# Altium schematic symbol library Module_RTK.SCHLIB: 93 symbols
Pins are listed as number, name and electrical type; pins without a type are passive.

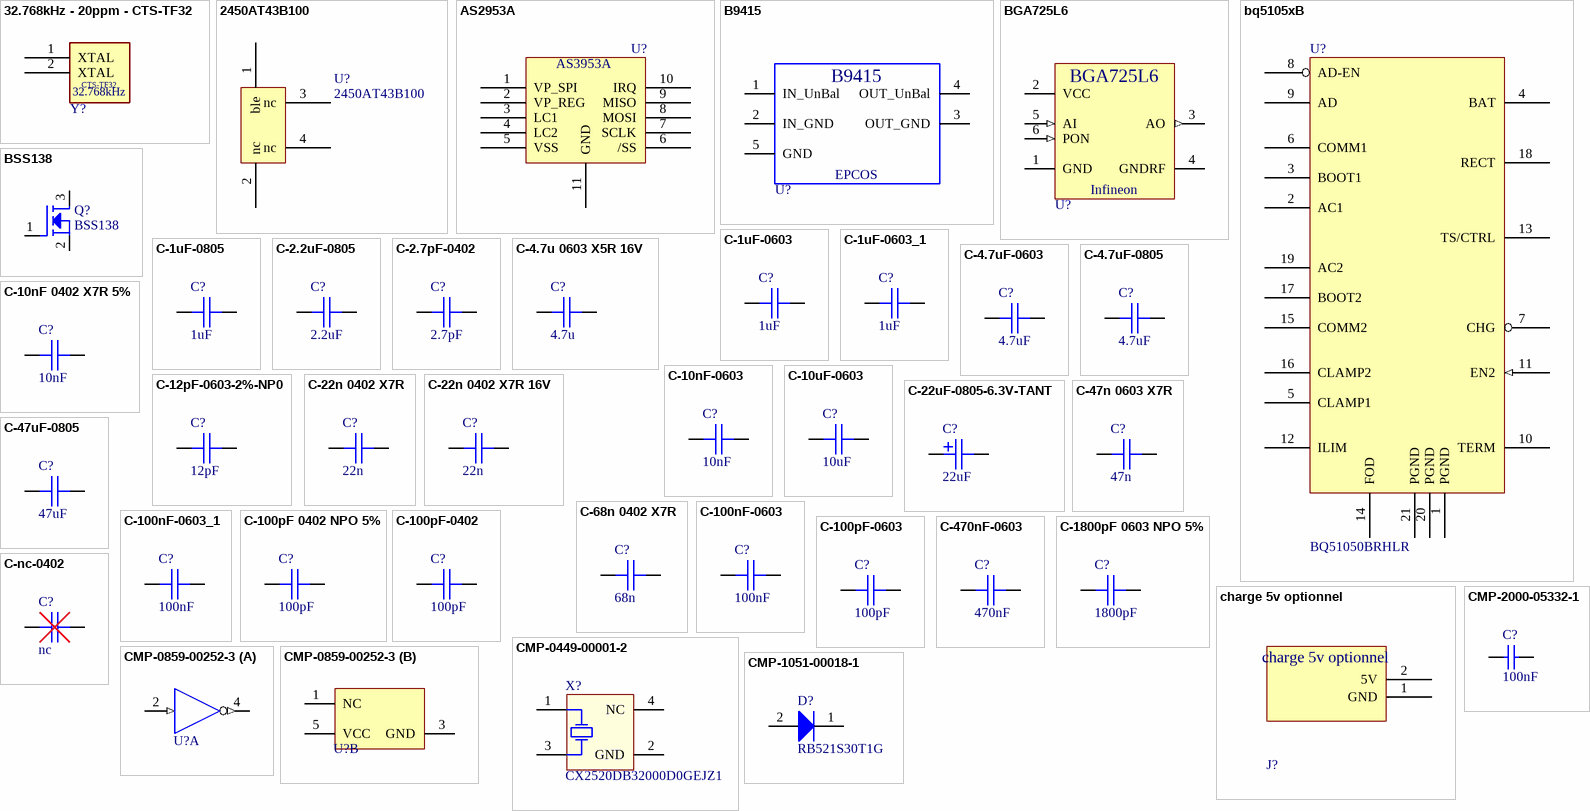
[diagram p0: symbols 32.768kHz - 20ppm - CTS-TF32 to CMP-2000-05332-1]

## 32.768kHz - 20ppm - CTS-TF32
designator Y?  (value not drawn)
footprint CTS-TF32 (3.2mm x 1.5mm)
pins: 1 XTAL, 2 XTAL

## 2450AT43B100
designator U?
ble ant 2.4 GHz
footprint 2450AT43B100 (ble ant 2.4 GHz)
pins: 1 ble, 2 nc, 3 nc, 4 nc

## AS2953A
designator U?, comment AS3953A  (value not drawn)
footprint MLPD_3x3mm_10_pin_AS3953A (PSON, 10-Leads, Body 3,00x3,00mm, Pitch 0,50mm, Thermal Pad 2,36x1,63mm, IPC Medium Density)
pins: 1 VP_SPI, 2 VP_REG, 3 LC1, 4 LC2, 5 VSS, 6 /SS, 7 SCLK, 8 MOSI, 9 MISO, 10 IRQ, 11 GND

## B9415
designator U?  (value not drawn)
SAW filter; PartNumber: BGA725L6; Manufacturer: Infineon; Gain (typ): 20 dB; F (typ): 0.65 dB; I (typ): 3.6 mA; Frequency (f): 1550 - 1615 MHz; Green: yes; P-1dB (in): -16
footprint B9415
pins: 1 IN_UnBal (power) "General ground", 2 IN_GND (power) "DC supply", 3 OUT_GND (power) "DC supply", 4 OUT_UnBal (power) "LNA RF ground", 5 GND (power) "DC supply"

## BGA725L6
designator U?  (value not drawn)
Silicon Germanium Low Noise Amplifier for Global Navigation Satellite Systems (GNSS), 1550 - 1615 MHz, 20 dB Gain, TSLP-6-2, Green; Manufacturer: Infineon; Gain (typ): 20 dB; F (typ): 0.65 dB; I (typ): 3.6 mA; Green: yes; P-1dB (in): -16
footprint INF-TSLP-6-2_V (TSLP, 6-Leads, Body 0.7x1.1 mm)
pins: 1 GND (power) "General ground", 2 VCC (power) "DC supply", 3 AO (out) "LNA output", 4 GNDRF (power) "LNA RF ground", 5 AI (in) "LNA input", 6 PON (in) "Power on control"

## bq5105xB
designator U?, comment BQ51050BRHLR
footprint RHL20-3050X2050TP (QFN, 20-Leads, Body 4.5x3.5mm, Pitch 0.5mm, Thermal Pad 3.05x2.05mm, TI Recommended)
pins: 1 PGND (power), 2 AC1, 3 BOOT1, 4 BAT, 5 CLAMP1, 6 COMM1, 7 CHG (oc), 8 AD-EN, 9 AD, 10 TERM, 11 EN2 (in), 12 ILIM, 13 TS/CTRL, 14 FOD, 15 COMM2, 16 CLAMP2, 17 BOOT2, 18 RECT, 19 AC2, 20 PGND (power), 21 PGND (power)

## BSS138
designator Q?
MOSFET N-CH 50V 200MA SOT23-3; Manufacturer: Diodes Inc; RefMfg: BSS138-7-F
footprint SOT23_0.915
pins: 1 G, 2 S, 3 D

## C-1uF-0603
designator C?  value 1uF  (hidden comment: C-1uF-0603)
Voltage: 25V; Fabricant_Ref: GRM188R71E104JA01D; Fabricant: Murata; Technologie: 5%
simulation model CAP
footprint SM/C_0603
pins: 1, 2
1 alternate drawing of the same symbol

## C-1uF-0603_1
designator C?, comment value 1uF  (hidden comment: C-1uF-0603)
Voltage: 16V; Fabricant_Ref: C1608X7R1C105K080AC; Fabricant: Murata; Tolerance: 10%; Technologie: X7R
simulation model CAP
footprint SM/C_0603
pins: 1, 2
1 alternate drawing of the same symbol

## C-1uF-0805
designator C?  value 1uF  (hidden comment: C-1uF-0805)
Voltage: 16V; Fabricant_Ref: GRM188R71E104JA01D; Fabricant: Murata; Tolerance: 10%; Technologie: X7R
simulation model CAP
footprint SM/C_0805
pins: 1, 2
1 alternate drawing of the same symbol

## C-2.2uF-0805
designator C?  value 2.2uF  (hidden comment: C-2.2uF-0805)
Voltage: 16V; Fabricant_Ref: C2012X7R1C225K125AB; Fabricant: Murata; Tolerance: 10%; Technologie: X7R
simulation model CAP
footprint SM/C_0805
pins: 1, 2
1 alternate drawing of the same symbol

## C-2.7pF-0402
designator C?  value 2.7pF  (hidden comment: C-2.7pF-0402)
Voltage: 50V; Fabricant_Ref: GRM1555C1H2R7BA01D; Fabricant: Murata; Tolerance: 0.1pF; Technologie: NPO
simulation model CAP
footprint SM/C_0402
pins: 1, 2
1 alternate drawing of the same symbol

## C-4.7u 0603 X5R 16V
designator C?  value 4.7u  (hidden comment: C-4.7u 0603 X5R 16V)
Fabricant_Ref: GRM188R61C475KAAJD; Fabricant: Murata; Tolerance: 10%
simulation model CAP
footprint SM/C_0603
pins: 1, 2
1 alternate drawing of the same symbol

## C-4.7uF-0603
designator C?  value 4.7uF  (hidden comment: C-4.7uF-0603)
Voltage: 6.3V; Fabricant_Ref: GRM188R60J475KE19D; Fabricant: Murata; Tolerance: 10%; Technologie: X5R
simulation model CAP
footprint SM/C_0603
pins: 1, 2
1 alternate drawing of the same symbol

## C-4.7uF-0805
designator C?  value 4.7uF  (hidden comment: C-4.7uF-0805)
Voltage: 10V; Fabricant_Ref: C2012X7R1A475K085AC; Fabricant: Murata; Tolerance: 10%; Technologie: X7R
simulation model CAP
footprint SM/C_0805
pins: 1, 2
1 alternate drawing of the same symbol

## C-10nF 0402 X7R 5%
designator C?  value 10nF  (hidden comment: C-10nF 0402 X7R 5%)
Voltage: 50V; Fabricant_Ref: C0402C103J5RACTU; Fabricant: KEMET
simulation model CAP
footprint SM/C_0402
pins: 1, 2
1 alternate drawing of the same symbol

## C-10nF-0603
designator C?  value 10nF  (hidden comment: C-10nF-0603)
Voltage: 50V; Fabricant_Ref: GRM188R71H103KA01D; Fabricant: Murata; Tolerance: 10%; Technologie: X7R
simulation model CAP
footprint SM/C_0603
pins: 1, 2
1 alternate drawing of the same symbol

## C-10uF-0603
designator C?  value 10uF  (hidden comment: C-10uF-0603)
Voltage: 6.3V; Fabricant_Ref: C1608X5R0J106M080AB; Fabricant: TDK; Tolerance: 20%; Technologie: X5R
simulation model CAP
footprint SM/C_0603
pins: 1, 2
1 alternate drawing of the same symbol

## C-12pF-0603-2%-NP0
designator C?  value 12pF  (hidden comment: C-12pF-0603-2%-NP0)
Fabricant: Murata; Fabricant_Ref: GRM1885C1H220JA01D; Technologie: NPO; Tolerance: 5%; Voltage: 50V
footprint SM/C_0603 (Footprint not found)
pins: 1, 2

## C-22n 0402 X7R
designator C?  value 22n  (hidden comment: C-22n 0402 X7R)
Voltage: 50V; Fabricant_Ref: GRM155R71H223KA12D; Fabricant: Murata; Tolerance: 10%
simulation model CAP
footprint SM/C_0402
pins: 1, 2
1 alternate drawing of the same symbol

## C-22n 0402 X7R 16V
designator C?  value 22n  (hidden comment: C-22n 0402 X7R 16V)
Fabricant_Ref: 0402YC223KAT2A; Fabricant: AVX; Tolerance: 10%
simulation model CAP
footprint SM/C_0402
pins: 1, 2
1 alternate drawing of the same symbol

## C-22uF-0805-6.3V-TANT
designator C?  value 22uF  (hidden comment: C-22uF-0805-6.3V-TANT)
Voltage: 6.3V; Fabricant_Ref: TLJP107M006R5400; Fabricant: AVX; Tolerance: 20%; Technologie: Tantale
simulation model CAP
footprint SM/C_0805_POL
pins: 1, 2
1 alternate drawing of the same symbol

## C-47n 0603 X7R
designator C?  value 47n  (hidden comment: C-47n 0603 X7R)
Voltage: 50V; Fabricant_Ref: GRM188R71H473KA61D; Fabricant: Murata; Tolerance: 10%
simulation model CAP
footprint SM/C_0603
pins: 1, 2
1 alternate drawing of the same symbol

## C-47uF-0805
designator C?  value 47uF  (hidden comment: C-47uF-0805)
Voltage: 6.3V; Fabricant_Ref: C2012X5R0J476M125AC; Fabricant: TDK; Tolerance: 20%; Technologie: X5R
simulation model CAP
footprint SM/C_0805
pins: 1, 2
1 alternate drawing of the same symbol

## C-68n 0402 X7R
designator C?  value 68n  (hidden comment: C-68n 0402 X7R)
Voltage: 50V; Fabricant_Ref: C1005X7R1H683K050BB; Fabricant: TDK; Tolerance: 10%
simulation model CAP
footprint SM/C_0402
pins: 1, 2
1 alternate drawing of the same symbol

## C-100nF-0603
designator C?  value 100nF  (hidden comment: C-100nF-0603)
Voltage: 25V; Fabricant_Ref: GRM188R71E104JA01D; Fabricant: Murata; Technologie: 5%
simulation model CAP
footprint SM/C_0603
pins: 1, 2
1 alternate drawing of the same symbol

## C-100nF-0603_1
designator C?, comment value 100nF  (hidden comment: C-100nF-0603)
Voltage: 25V; Fabricant_Ref: C1608X7R1E104K080AA; Fabricant: TDK; Tolerance: 10%; Technologie: X7R
simulation model CAP
footprint SM/C_0603
pins: 1, 2
1 alternate drawing of the same symbol

## C-100pF 0402 NPO 5%
designator C?  value 100pF  (hidden comment: C-100pF 0402 NPO 5%)
Voltage: 50V; Fabricant_Ref: 500R07N101JV4T; Fabricant: Johanson Dielectrics
simulation model CAP
footprint SM/C_0402
pins: 1, 2
1 alternate drawing of the same symbol

## C-100pF-0402
designator C?  value 100pF  (hidden comment: C-100pF-0402)
Voltage: 50V; Fabricant_Ref: GRM1555C1H101FA01J; Fabricant: Murata; Tolerance: 1%; Technologie: NPO
simulation model CAP
footprint SM/C_0402
pins: 1, 2
1 alternate drawing of the same symbol

## C-100pF-0603
designator C?  value 100pF  (hidden comment: C-100pF-0603)
Voltage: 100V; Fabricant_Ref: GRM1885C2A101JA01D; Fabricant: Murata; Tolerance: 5%; Technologie: NPO
simulation model CAP
footprint SM/C_0603
pins: 1, 2
1 alternate drawing of the same symbol

## C-470nF-0603
designator C?  value 470nF  (hidden comment: C-470nF-0603)
Fabricant: Samsung; Fabricant_Ref: CL10B104JA8NNNC; Technologie: X7R; Tolerance: 5%; Voltage: 25V
footprint SM/C_0603 (Footprint not found)
pins: 1, 2

## C-1800pF 0603 NPO 5%
designator C?  value 1800pF  (hidden comment: C-1800pF 0603 NPO 5%)
Voltage: 50V; Fabricant_Ref: GRM1885C1H182JA01D; Fabricant: Murata
simulation model CAP
footprint SM/C_0603
pins: 1, 2
1 alternate drawing of the same symbol

## C-nc-0402
designator C?  value nc  (hidden comment: C-nc-0402)
Technologie: NPO
simulation model CAP
footprint SM/C_0402 (Footprint not found)
pins: 1, 2
1 alternate drawing of the same symbol

## charge 5v optionnel
designator J?  (value not drawn)
connecteur de charge 5v si jamais il y avais des problemes avec la charge par induction. (fils a souder directement sur le pcb, pas de connecteur externe)
pins: 1 GND, 2 5V

## CMP-0449-00001-2
designator X?, comment CX2520DB32000D0GEJZ1
Crystal, 32 MHz, 8 pF, -10 to 70 degC, Surface Mount 2.5 x 2.0 mm; Manufacturer: Kyocera; Manufacturer 1: Kyocera AVX; Load Capacitance: 8 pF; Frequency Range: 32000 kHz; Packing: Tape and Reel; Motional Series Resistance: 50 ohm (max); Drive Level: 10uW (100uW max.)
footprint AVX-CX2520DB32000D0GEJZ1-4_V (Hand Drawn, 4-Leads,Body 2.5x2mm)
pins: 1 HOT, 2 GND (power), 3 HOT, 4 NC

## CMP-0859-00252-3
designator U?, comment SN74LVC1G04DCKR  (value not drawn)
Single Inverter, DCK0005A, LARGE T&R; Manufacturer: Texas Instruments; Input Type: CMOS/TTL; Output Drive (IOL/IOH)(Max)(mA): 32/-32; Sub-Family: Inverting Buffer/Driver; VCC(Min)(V): 1.65; Bits(#): 1; Schmitt Trigger: No; Technology Family: LVC; Rating: Catalog; ICC @ Nom Voltage(Max)(mA): 0.01; tpd @ Nom Voltage(Max)(ns): 7.5,5.2,4.2,3.7; Voltage(Nom)(V): 1.8,2.5,3.3,5; F @ Nom Voltage(Max)(Mhz): 150; Output Type: CMOS; VCC(Max)(V): 5.5; Logic: Inverting
footprint DCK0005A_N (SOT23, 5-Leads, Body 2.15x1.4mm, Pitch 0.65mm, IPC Medium Density)
footprint DCK0005A_L (SOT23, 5-Leads, Body 2.15x1.4mm, Pitch 0.65mm, IPC High Density)
footprint DCK0005A_M (SOT23, 5-Leads, Body 2.15x1.4mm, Pitch 0.65mm, IPC Low Density)
part A pins: 2 A (in) "Input A", 4 Y (out) "Output Y"
part B pins: 1 NC "Ground", 3 GND (power) "Ground Pin", 5 VCC (power) "Power Pin"

## CMP-1051-00018-1
designator D?, comment RB521S30T1G
Schottky Barrier Diode, 2-Pin SOD-523, Pb-Free, Tape and Reel; Manufacturer: On Semiconductor; Configuration: Single; IFSM Max (A): 1
footprint ONSC-SOD-523-2-502-01_V (SOD, 2-Leads, Body 1.2x0.8mm)
pins: 1 K, 2 A

## CMP-2000-05332-1
designator C?, comment 100nF
Multi-layer Ceramic Capacitor, -55 to 125 degC, 2-Pin SMD (0603), RoHS, Tape and Reel; Manufacturer: Samsung Electro-Mechanics; Manufacturer 1: Samsung; Manufacturer Part Number 1: CL10B104KB8NNNC; Capacitance: 0.1µF; Rated Voltage: 50V; Dielectric: X7R; Tolerance (%): ±10%
footprint SAMS-C0603-2_M (Chip Capacitor, 2-Leads, Body 1.70x0.90mm, IPC Low Density)
footprint SAMS-C0603-2_N (Footprint not found)
footprint SAMS-C0603-2_L (Chip Capacitor, 2-Leads, Body 1.70x0.90mm, IPC High Density)
pins: 1, 2

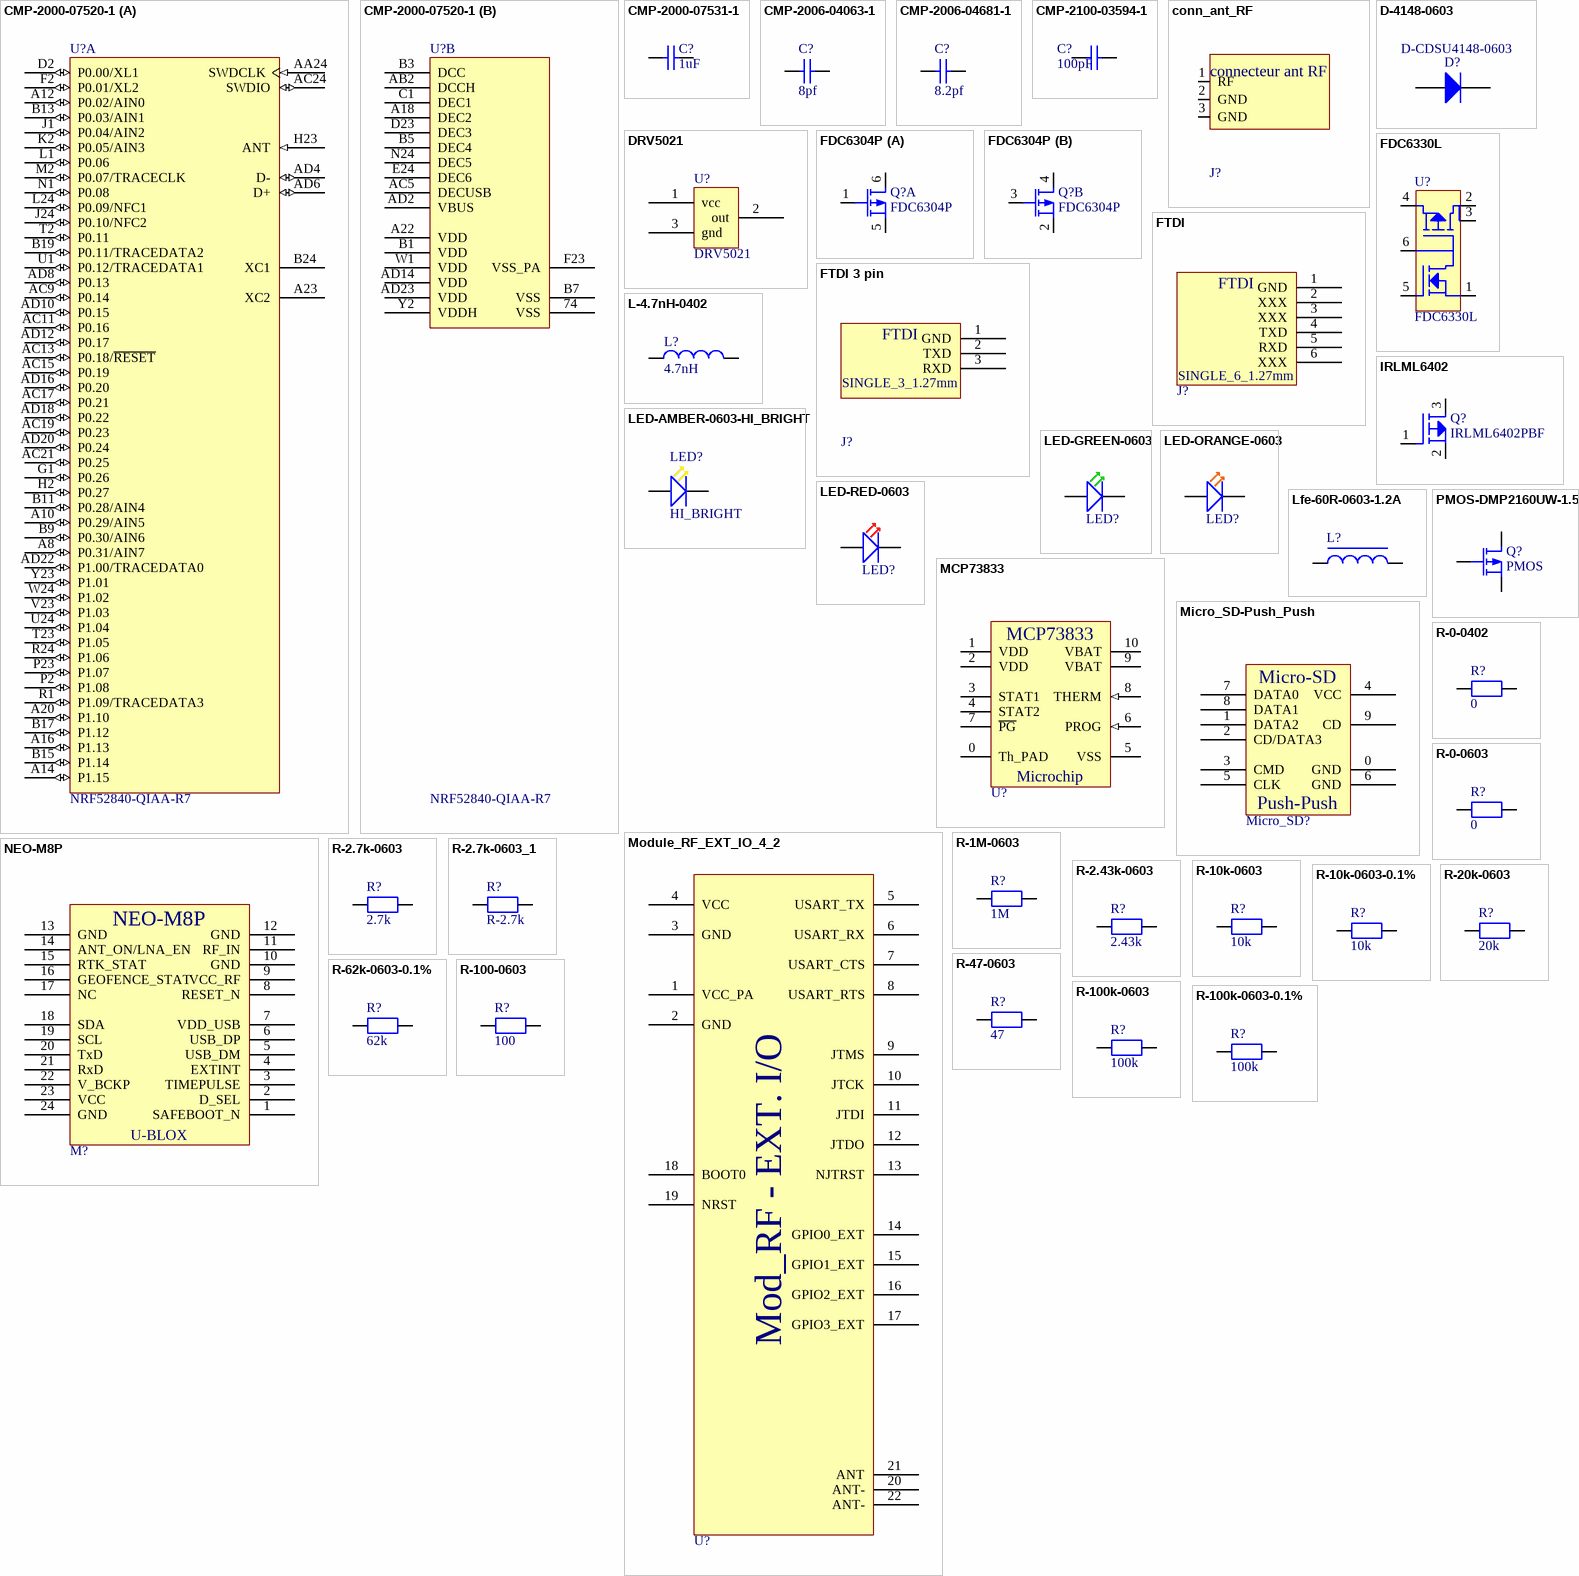
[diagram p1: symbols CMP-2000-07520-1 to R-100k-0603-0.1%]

## CMP-2000-07520-1
designator U?, comment NRF52840-QIAA-R7
RF System on a Chip, 1.7 to 3.6 V, -40 to 85 degC, 73-Pin AQFN, RoHS, Tape and Reel; Manufacturer: Nordic Semiconductor
footprint NRSC-AQFN-73 (AQFN, 73-Leads, Body 7x7mm, Pitch 0.5mm)
part A pins: A8 P0.31/AIN7 (io), A10 P0.29/AIN5 (io), A12 P0.02/AIN0 (io), A14 P1.15 (io) "General purpose I/O", A16 P1.13 (io) "General purpose I/O", A20 P1.10 (io) "General purpose I/O", A23 XC2 "Connection for 32 MHz crystal.", AA24 SWDCLK (in) "Serial wire debug clock input for debug and programming", AC9 P0.14 (io) "General purpose I/O", AC11 P0.16 (io) "General purpose I/O", AC13 P0.18/~{RESET} (io), AC15 P0.19 (io) "General purpose I/O", AC17 P0.21 (io) "General purpose I/O", AC19 P0.23 (io) "General purpose I/O", AC21 P0.25 (io) "General purpose I/O", AC24 SWDIO (io) "Debug serial data", AD4 D- (io) "USB D-", AD6 D+ (io) "USB D+", AD8 P0.13 (io) "General purpose I/O", AD10 P0.15 (io) "General purpose I/O", AD12 P0.17 (io) "General purpose I/O", AD16 P0.20 (io) "General purpose I/O", AD18 P0.22 (io) "General purpose I/O", AD20 P0.24 (io) "General purpose I/O", AD22 P1.00/TRACEDATA0 (io), B9 P0.30/AIN6 (io), B11 P0.28/AIN4 (io), B13 P0.03/AIN1 (io), B15 P1.14 (io) "General purpose I/O", B17 P1.12 (io) "General purpose I/O", B19 P0.11/TRACEDATA2 (io), B24 XC1 "Connection for 32 MHz crystal", D2 P0.00/XL1 (io), F2 P0.01/XL2 (io), G1 P0.26 (io) "General purpose I/O", H2 P0.27 (io) "General purpose I/O", H23 ANT (in) "Single-ended radio antenna connection", J1 P0.04/AIN2 (io), J24 P0.10/NFC2 (io), K2 P0.05/AIN3 (io), L1 P0.06 (io) "General purpose I/O", L24 P0.09/NFC1 (io), M2 P0.07/TRACECLK (io), N1 P0.08 (io) "General purpose I/O", P2 P1.08 (io) "General purpose I/O", P23 P1.07 (io) "General purpose I/O", R1 P1.09/TRACEDATA3 (io), R24 P1.06 (io) "General purpose I/O", T2 P0.11 (io) "General purpose I/O", T23 P1.05 (io) "General purpose I/O", U1 P0.12/TRACEDATA1 (io), U24 P1.04 (io) "General purpose I/O", V23 P1.03 (io) "General purpose I/O", W24 P1.02 (io) "General purpose I/O", Y23 P1.01 (io) "General purpose I/O"
part B pins: 74 VSS (power) "Ground pad. Exposed die pad must be connected to ground (VSS) for proper device operation.", A18 DEC2 (power) "1.3 V regulator supply decoupling (Radio supply)", A22 VDD (power) "Power supply", AB2 DCCH (power) "DC/DC converter output", AC5 DECUSB (power) "Decoupling for USB 3.3 V", AD2 VBUS (power) "5 V input for USB 3.3 V regulator", AD14 VDD (power) "Power supply", AD23 VDD (power) "Flash supply pad", B1 VDD (power) "Power supply", B3 DCC (power) "DC/DC converter output", B5 DEC4 (power) "1.3 V regulator supply decoupling", B7 VSS (power) "Ground", C1 DEC1 (power) "1.1 V regulator supply decoupling", D23 DEC3 (power) "Power supply, decoupling", E24 DEC6 (power) "1.3 V regulator supply decoupling (Radio supply)", F23 VSS_PA (power) "Ground (Radio supply)", N24 DEC5 (power) "1.3 V regulator supply decoupling (flash supply)", W1 VDD (power) "Power supply", Y2 VDDH (power) "High voltage power supply"

## CMP-2000-07531-1
designator C?, comment 1uF
Chip Capacitor, 1 uF, +/- 10%, 50 V, -55 to 125 degC, 0603 (1608 Metric), RoHS, Tape and Reel; Manufacturer: Taiyo Yuden; Manufacturer Part Number 1: UMK107AB7105KA-T; Voltage Rating: 50V; Dielectric: X7R
footprint CAPC1709X95X35LL10T25 (Chip Capacitor, 2-Leads, Body 1.75x0.95mm, IPC High Density)
footprint CAPC1709X95X35ML10T25 (Chip Capacitor, 2-Leads, Body 1.75x0.95mm, IPC Low Density)
footprint CAPC1709X95X35NL10T25 (Chip Capacitor, 2-Leads, Body 1.75x0.95mm, IPC Medium Density)
pins: 1, 2

## CMP-2006-04063-1
designator C?, comment 8pf
Manufacturer: AVX Interconnect / Elco; Part Number: 06031A8R0CAT2A; Manufacturer 1: Kyocera AVX
footprint CAPC1608X90X35LL15T15 (Chip Capacitor, 2-Leads, Body 1.60x0.81mm, IPC High Density)
footprint CAPC1608X90X35NL15T15 (Chip Capacitor, 2-Leads, Body 1.60x0.81mm, IPC Medium Density)
footprint CAPC1608X90X35ML15T15 (Chip Capacitor, 2-Leads, Body 1.60x0.81mm, IPC Low Density)
pins: 1, 2
1 alternate drawing of the same symbol

## CMP-2006-04681-1
designator C?, comment value 8.2pf  (hidden comment: 06032U8R2CAT2A)
Manufacturer: AVX Interconnect / Elco; Manufacturer 1: Kyocera AVX
footprint CAPC1508X91X25LL25T13 (Chip Capacitor, 2-Leads, Body 1.52x0.76mm, IPC High Density)
footprint CAPC1508X91X25ML25T13 (Chip Capacitor, 2-Leads, Body 1.52x0.76mm, IPC Low Density)
footprint CAPC1508X91X25NL25T13 (Chip Capacitor, 2-Leads, Body 1.52x0.76mm, IPC Medium Density)
pins: 1, 2
1 alternate drawing of the same symbol

## CMP-2100-03594-1
designator C?, comment Capacitance: 100pF  (hidden comment: CC0603JRNPO9BN101)
Chip Capacitor, 100 pF, +/- 5%, 50 V, -55 to 125 degC, 0603 (1608 Metric), RoHS, Tape and Reel; Manufacturer: Yageo; Voltage Rating (DC): 50V; Dielectric: C0G; Temperature Coefficient: 30ppm/degC; Insulation Resistance: 100GR
footprint CAPC1608X90X40ML10T20 (Chip Capacitor, 2-Leads, Body 1.7x0.9mm, IPC Low Density)
footprint CAPC1608X90X40NL10T20 (Chip Capacitor, 2-Leads, Body 1.60x0.80mm, IPC Medium Density)
footprint SM/C_0603
pins: 1, 2

## conn_ant_RF
designator J?, comment FTDI  (value not drawn)
pins: 1 RF, 2 GND, 3 GND

## D-4148-0603
designator D?, comment D-CDSU4148-0603
Fabricant: Comchip Technology; Fabricant_Ref: CSDU4148
footprint 0603/SOD-523F_Diode (SODFL, 2-Leads, Body 0,90x1,70mm, IPC Medium Density)
pins: 1 A, 2 K

## DRV5021
designator U?
Hall Effect Sensor
footprint SOT23 (SOT23, 3-Leads, Body 2,90x2,45mm, Pitch 0,95mm, IPC Medium Density)
pins: 1 vcc, 2 out, 3 gnd

## FDC6304P
designator Q?
Fabricant: Fairschild
footprint supersot_6
part A pins: 1 G1, 5 S1, 6 D1
part B pins: 2 S2, 3 G2, 4 D2

## FDC6330L
designator U?
IC LOAD SWITCH INT 20VIN SSOT-6; Manufacturer: Fairchild Semiconductor
footprint SOT-363_0.95 (TSOT-23, 6-Leads, Body 2.90x1.63mm, Pitch 0.95mm, IPC Medium Density)
pins: 1 R2, 2 D1Vout, 3 Vout, 4 Vin, 5 ON/OFF, 6 R1C1

## FTDI
designator J?  (value not drawn)
footprint SINGLE_6_1.27mm (Connector; Header; 6 Position)
pins: 1 GND, 2 XXX, 3 XXX, 4 TXD, 5 RXD, 6 XXX

## FTDI 3 pin
designator J?, comment FTDI  (value not drawn)
pins: 1 GND, 2 TXD, 3 RXD

## IRLML6402
designator Q?, comment IRLML6402PBF
MOSFET P-CH 20V 3.7A SOT-23; Manufacturer: International Rectifier; RefMfg: IRLML6402TRPBF
footprint SOT23_0.915
pins: 1 G, 2 S, 3 D

## L-4.7nH-0402
designator L?  value 4.7nH  (hidden comment: L-4.7nH-0402)
I_DC: 300mA; Tolerance: 0.3nH; Fabricant: Murata; Fabricant_Ref: LQG15HN3N3S02D
simulation model Model Name (Model Description)
footprint SM/L_0402
pins: 1, 2

## LED-AMBER-0603-HI_BRIGHT
designator LED?  (value not drawn)
footprint SM/D_0603 (Diode Package 0603)
pins: 1 A, 2 K

## LED-GREEN-0603
designator LED?  (value not drawn)
footprint SM/D_0603 (Diode Package 0603)
pins: 1 A, 2 K

## LED-ORANGE-0603
designator LED?  (value not drawn)
footprint SM/D_0603 (Diode Package 0603)
pins: 1 A, 2 K

## LED-RED-0603
designator LED?  (value not drawn)
footprint SM/D_0603 (Diode Package 0603)
pins: 1 A, 2 K

## Lfe-60R-0603-1.2A
designator L?  (value not drawn)
¦Z¦>200[Ω]@1.5[GHz]; I_DC: 1300mA; Tolerance: 20%; Fabricant: TDK; Fabricant_Ref: MLP2012HR47MT0S1; Value: Beads
simulation model Model Name (Model Description)
footprint SM/L_0603 (1608)
pins: 1, 2

## MCP73833
designator U?  (value not drawn)
Stand-Alone Linear Li-Ion/Li-Polymer Charge Management Controller with Power-Good Output, 4.2V, 10-Pin DFN, Industrial Temperature
footprint DFN-MF10 (SON, 10-Leads, Body 3x3mm, Pitch 0.5mm, Microchip Recommended)
pins: 0 Th_PAD (power), 1 VDD (power), 2 VDD (power), 3 STAT1 (oc), 4 STAT2 (oc), 5 VSS (power), 6 PROG (in), 7 ~{PG} (oc), 8 THERM (in), 9 VBAT (power), 10 VBAT (power)

## Micro_SD-Push_Push
designator Micro_SD?  (value not drawn)
Fabricant: ALPS; Fabricant_Ref: SCHD3A0100
footprint Amphenol-10100660 (Micro-SD)
pins: 0 GND, 1 DATA2, 2 CD/DATA3, 3 CMD, 4 VCC, 5 CLK, 6 GND, 7 DATA0, 8 DATA1, 9 CD

## Module_RF_EXT_IO_4_2
designator U?  (value not drawn)
Pour la conception du module RF
footprint PadRing_RF4_2 (Pad ring for YLX_RF_4_2)
footprint Module_RF4_2
pins: 1 VCC_PA, 2 GND, 3 GND, 4 VCC, 5 USART_TX, 6 USART_RX, 7 USART_CTS, 8 USART_RTS, 9 JTMS, 10 JTCK, 11 JTDI, 12 JTDO, 13 NJTRST, 14 GPIO0_EXT, 15 GPIO1_EXT, 16 GPIO2_EXT, 17 GPIO3_EXT, 18 BOOT0, 19 NRST, 20 ANT-, 21 ANT, 22 ANT-

## NEO-M8P
designator M?, comment NEO-M8P NEW!!  (value not drawn)
NEW !! GNSS module for GPS/QZSS, GLONASS
footprint NEO-7 (GNSS module for GPS/QZSS, GLONASS)
pins: 1 SAFEBOOT_N, 2 D_SEL, 3 TIMEPULSE, 4 EXTINT, 5 USB_DM, 6 USB_DP, 7 VDD_USB, 8 RESET_N, 9 VCC_RF, 10 GND, 11 RF_IN, 12 GND, 13 GND, 14 ANT_ON/LNA_EN, 15 RTK_STAT, 16 GEOFENCE_STAT, 17 NC, 18 SDA, 19 SCL, 20 TxD, 21 RxD, 22 V_BCKP, 23 VCC, 24 GND

## PMOS-DMP2160UW-1.5A
designator Q?, comment PMOS
Low RDS(ON)
footprint SOT-323
pins: 1 G, 2 S, 3 D

## R-0-0402
designator R?  value 0  (hidden comment: R-0-0402)
Fabricant_Ref: ERJ-2GE0R00X; Fabricant: Panasonic; Puissance: 100 mW; Tolerance: 1%; Tension: 50V
signal-integrity model Res
footprint SM/R_0402
pins: 1, 2

## R-0-0603
designator R?  value 0  (hidden comment: R-0-0603)
Fabricant_Ref: ERJ-3GEY0R00V; Fabricant: Panasonic; Puissance: 100 mW; Tolerance: 1%; Tension: 50V
signal-integrity model Res
footprint SM/R_0603
pins: 1, 2

## R-1M-0603
designator R?  value 1M  (hidden comment: R-1M-0603)
Fabricant_Ref: ERJ-3EKF1004V; Fabricant: Panasonic; Puissance: 100 mW; Tolerance: 1%; Tension: 75V
signal-integrity model Res
footprint SM/R_0603
pins: 1, 2

## R-2.7k-0603
designator R?  value 2.7k  (hidden comment: R-2.7k-0603)
Fabricant: Panasonic; Puissance: 100 mW; Tolerance: 1%; Tension: 75V
signal-integrity model Res
footprint SM/R_0603
pins: 1, 2

## R-2.7k-0603_1
designator R?, comment value R-2.7k  (hidden comment: R-2.7k-0603)
Fabricant_Ref: ERJ-3EKF1501V; Fabricant: Panasonic; Puissance: 100 mW; Tolerance: 1%; Tension: 75V
signal-integrity model Res
footprint SM/R_0603
pins: 1, 2

## R-2.43k-0603
designator R?  value 2.43k  (hidden comment: R-2.43k-0603)
Fabricant_Ref: ERJ-3EKF2431V; Fabricant: Panasonic; Puissance: 100 mW; Tolerance: 1%; Tension: 75V
signal-integrity model Res
footprint SM/R_0603
pins: 1, 2

## R-10k-0603
designator R?  value 10k  (hidden comment: R-10k-0603)
Fabricant_Ref: ERJ-3EKF1002V; Fabricant: Panasonic; Puissance: 100 mW; Tolerance: 1%; Tension: 75V
signal-integrity model Res
footprint SM/R_0603
pins: 1, 2

## R-10k-0603-0.1%
designator R?  value 10k  (hidden comment: R-10k-0603-0.1%)
Fabricant_Ref: ERA-3AEB103V; Fabricant: Panasonic; Puissance: 100 mW; Tolerance: 0.1%; Tension: 75V
signal-integrity model Res
footprint SM/R_0603
pins: 1, 2

## R-20k-0603
designator R?  value 20k  (hidden comment: R-20k-0603)
Fabricant: Panasonic; Puissance: 100 mW; Tolerance: 1%; Tension: 75V
signal-integrity model Res
footprint SM/R_0603
pins: 1, 2

## R-47-0603
designator R?  value 47  (hidden comment: R-47-0603)
Fabricant_Ref: ERJ-3EKF47R0V; Fabricant: Panasonic; Puissance: 100 mW; Tolerance: 1%; Tension: 75V
signal-integrity model Res
footprint SM/R_0603
pins: 1, 2

## R-62k-0603-0.1%
designator R?  value 62k  (hidden comment: R-62k-0603-0.1%)
Fabricant_Ref: ERA-3AEB623V; Fabricant: Panasonic; Puissance: 100 mW; Tolerance: 0.1%; Tension: 75V
signal-integrity model Res
footprint SM/R_0603
pins: 1, 2

## R-100-0603
designator R?  value 100  (hidden comment: R-100-0603)
Fabricant_Ref: ERJ-3EKF1000V; Fabricant: Panasonic; Puissance: 100 mW; Tolerance: 1%; Tension: 75V
signal-integrity model Res
footprint SM/R_0603
pins: 1, 2

## R-100k-0603
designator R?  value 100k  (hidden comment: R-100k-0603)
Fabricant_Ref: ERJ-3EKF1003V; Fabricant: Panasonic; Puissance: 100 mW; Tolerance: 1%; Tension: 75V
signal-integrity model Res
footprint SM/R_0603
pins: 1, 2

## R-100k-0603-0.1%
designator R?  value 100k  (hidden comment: R-100k-0603-0.1%)
Fabricant_Ref: ERA-3AEB104V; Fabricant: Panasonic; Puissance: 100 mW; Tolerance: 0.1%; Tension: 75V
signal-integrity model Res
footprint SM/R_0603
pins: 1, 2

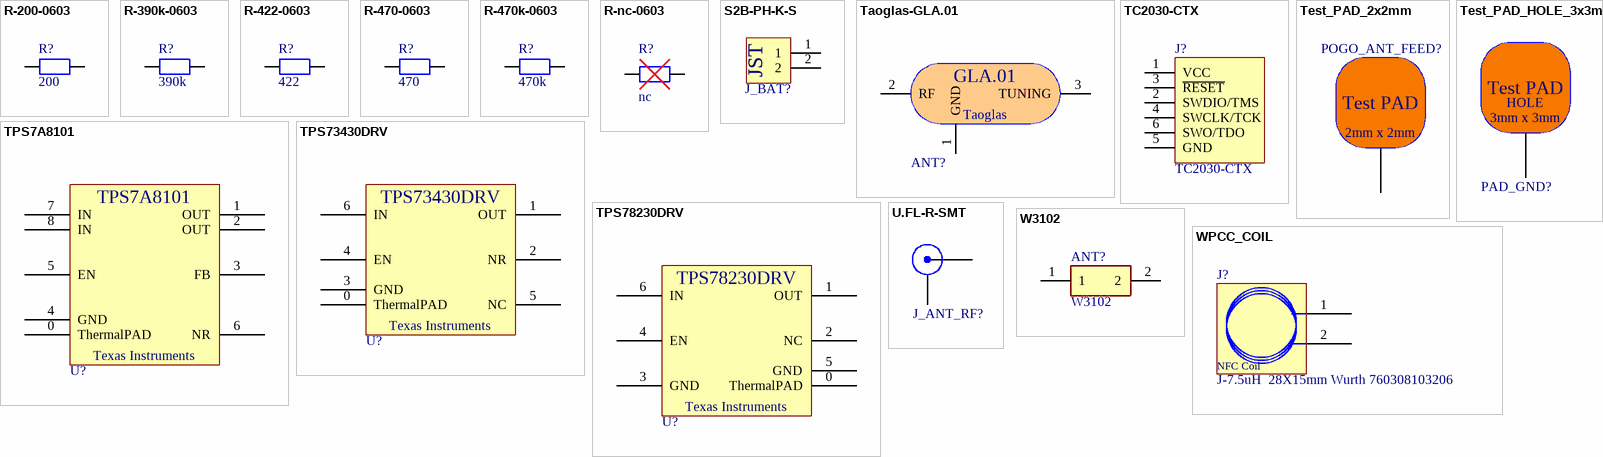
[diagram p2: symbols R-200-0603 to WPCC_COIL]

## R-200-0603
designator R?  value 200  (hidden comment: R-200-0603)
Fabricant_Ref: ERJ-3EKF2000V; Fabricant: Panasonic; Puissance: 100 mW; Tolerance: 1%; Tension: 75V
signal-integrity model Res
footprint SM/R_0603
pins: 1, 2

## R-390k-0603
designator R?  value 390k  (hidden comment: R-390k-0603)
Fabricant_Ref: ERJ-3EKF3903V; Fabricant: Panasonic; Puissance: 100 mW; Tolerance: 1%; Tension: 75V
signal-integrity model Res
footprint SM/R_0603
pins: 1, 2

## R-422-0603
designator R?  value 422  (hidden comment: R-422-0603)
Fabricant_Ref: ERJ-3EKF4220V; Fabricant: Panasonic; Puissance: 100 mW; Tolerance: 1%; Tension: 75V
signal-integrity model Res
footprint SM/R_0603
pins: 1, 2

## R-470-0603
designator R?  value 470  (hidden comment: R-470-0603)
Fabricant: Panasonic; Fabricant_Ref: ERJ-3EKF4700V; Tolerance: 1%
footprint SM/R_0603
pins: 1, 2

## R-470k-0603
designator R?  value 470k  (hidden comment: R-470k-0603)
Fabricant_Ref: ERJ-3EKF4703V; Fabricant: Panasonic; Puissance: 100 mW; Tolerance: 1%; Tension: 75V
signal-integrity model Res
footprint SM/R_0603
pins: 1, 2

## R-nc-0603
designator R?, comment value nc  (hidden comment: R-nc)
signal-integrity model Res
footprint SM/R_0603
pins: 1, 2

## S2B-PH-K-S
designator J_BAT?  (value not drawn)
JST, Through-Hole, Side entry type
footprint S2B-PH-K-S
pins: 1, 2

## Taoglas-GLA.01
designator ANT?  (value not drawn)
GPS Loop Antenna
footprint Taoglas-GLA.01
pins: 1 GND, 2 RF, 3 TUNING

## TC2030-CTX
designator J?  (no BOM)
ARM Cortex 10-pin Cable with 6-Pin TC2030 Plug-of-Nails Connector; Manufacturer: Tag-Connect; RefMfg: TC2030-IDC
footprint TC2030-IDC (Tag-Connect 6-Pin with Legs (PN# TC2030-IDC-NL))
pins: 1 VCC, 2 SWDIO/TMS, 3 ~{RESET}, 4 SWCLK/TCK, 5 GND, 6 SWO/TDO

## Test_PAD_2x2mm
designator POGO_ANT_FEED?  (value not drawn)
footprint Test_PAD_2x2mm
pins: 0

## Test_PAD_HOLE_3x3mm
designator PAD_GND?  (value not drawn)
footprint Test_PAD_HOLE_3x3mm
pins: 0

## TPS7A8101
designator U?  (value not drawn)
footprint SON-8_DRB (SON-8 DRB (TPS7A8001))
pins: 0 ThermalPAD, 1 OUT, 2 OUT, 3 FB, 4 GND, 5 EN, 6 NR, 7 IN, 8 IN

## TPS73430DRV
designator U?  (value not drawn)
footprint SON-6_DRV (SON-6 DRV (TPS73533))
pins: 0 ThermalPAD, 1 OUT, 2 NR, 3 GND, 4 EN, 5 NC, 6 IN

## TPS78230DRV
designator U?  (value not drawn)
footprint SON-6_DRV (SON-6 DRV (TPS73533))
pins: 0 ThermalPAD, 1 OUT, 2 NC, 3 GND, 4 EN, 5 GND, 6 IN

## U.FL-R-SMT
designator J_ANT_RF?  (value not drawn)
footprint U.FL-R-SMT
pins: 1 X, 2 Y

## W3102
designator ANT?
Antenna; Manufacturer_Name: PulseLarsen Antennas
footprint W3102
pins: 1, 2

## WPCC_COIL
designator J?, comment J-7.5uH  28X15mm Wurth 760308103206
Fabricant: Würth
footprint WE-WPCC (Wireless Power Charging  Receiver Coil)
pins: 1, 2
